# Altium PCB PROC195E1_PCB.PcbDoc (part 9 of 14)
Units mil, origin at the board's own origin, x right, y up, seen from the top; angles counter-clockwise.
Board outline 3110.24 x 2500 mil, 10 copper layers (Top Layer, L02_GND1, L03_SIG1, L04_GND2, L05_PWR1, L06_PWR2, L07_GND3, L08_SIG2, L09_GND4, Bottom Layer), stack 66.407 mil thick; 571 components, 538 nets, 6726 pads, 1286 vias.
Unrouted connection lines stored in the file: 4.
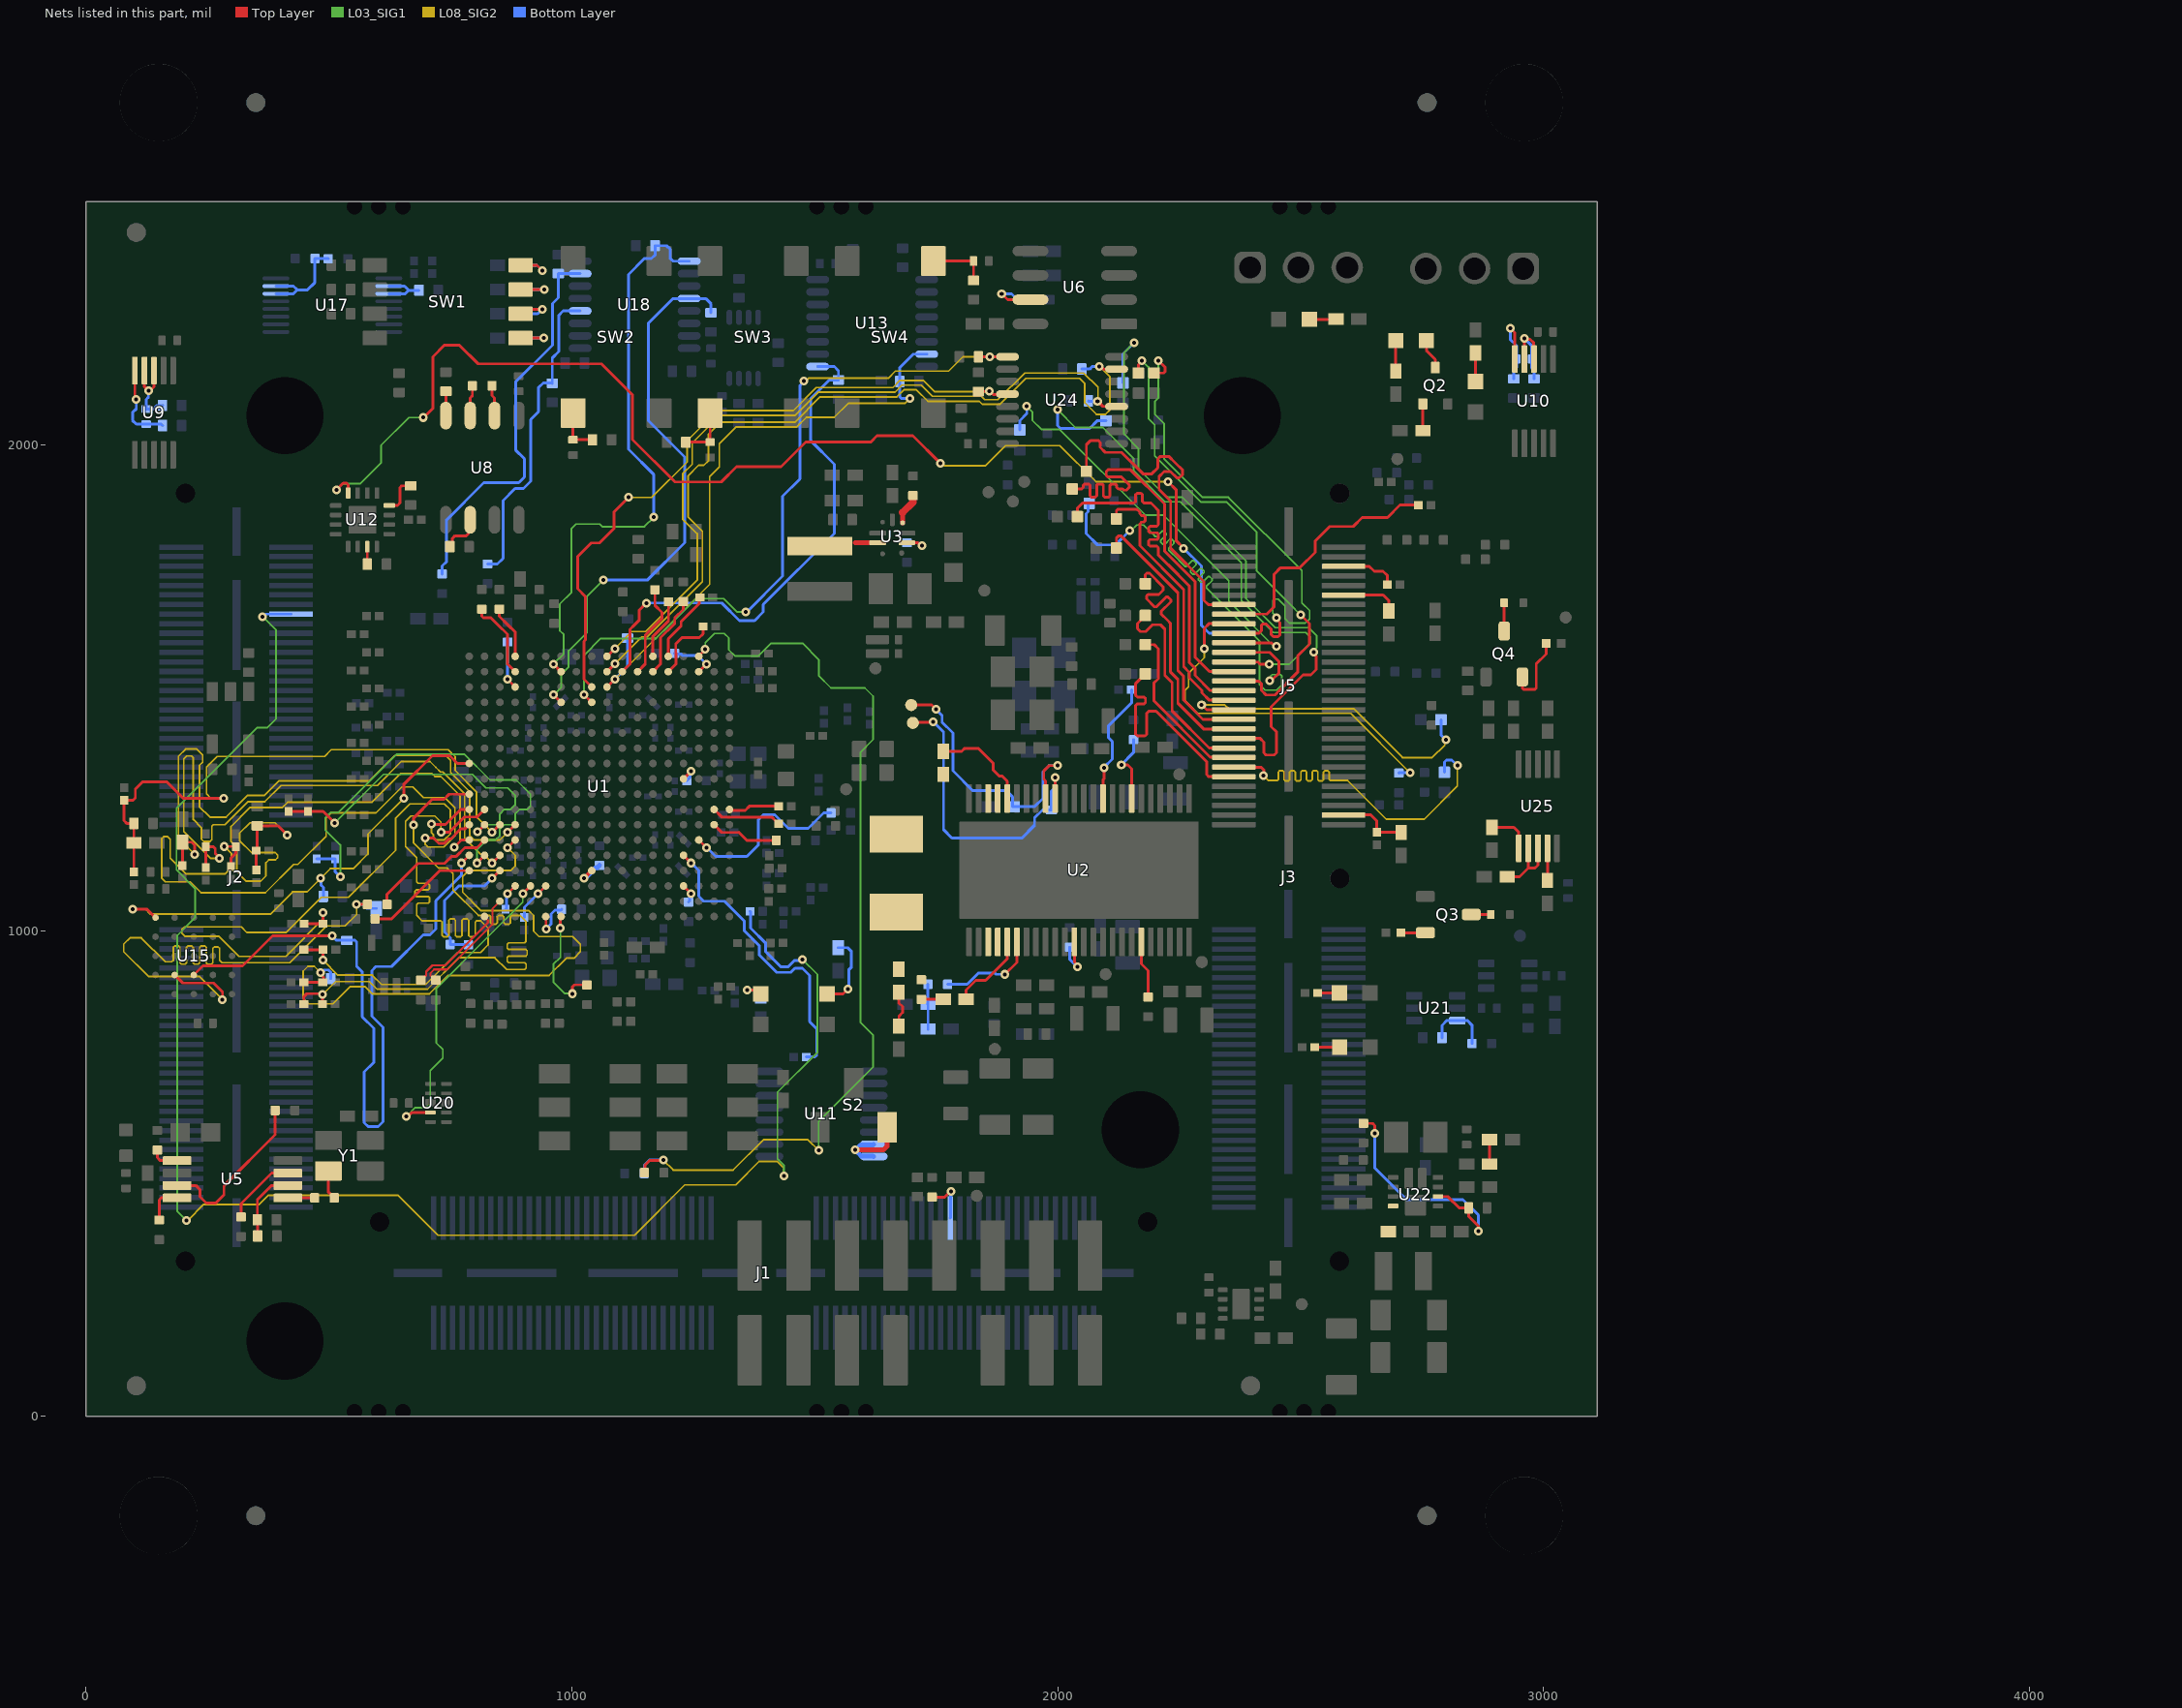
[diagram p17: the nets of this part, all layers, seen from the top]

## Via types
v1: diameter 18, hole 8, Top Layer to Bottom Layer, tented both sides, 1226 vias
v2: diameter 19.68, hole 7.87, Top Layer to Bottom Layer, tented top, 54 vias
v3: diameter 19.68, hole 7.87, Top Layer to Bottom Layer, 4 vias
v4: diameter 19.68, hole 7.87, Top Layer to Bottom Layer, tented both sides, 2 vias

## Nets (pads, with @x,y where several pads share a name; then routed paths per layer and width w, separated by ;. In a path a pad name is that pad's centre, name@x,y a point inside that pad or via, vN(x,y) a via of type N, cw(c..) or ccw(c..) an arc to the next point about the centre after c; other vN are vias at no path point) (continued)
MCU_SPI0_D0: R226.1 R299.2 U1.C10 U13.7 | length 1271.8
  Top Layer w5.8: U1.C10@1072.63,1501.41 v1(1088.66,1517.44)
  L08_SIG2 w3.6: v1(1088.66,1517.44) 1283.98,1712.77 1283.98,1934.28 1303.93,1954.22 1303.93,2002.31 1338.39,2036.77 1463.19,2036.77 1482.92,2056.5 1540.27,2056.5 1569.03,2085.26 1685.76,2085.26 v1(1695.92,2095.42)
  Bottom Layer w5.8: v1(1088.66,1517.44) 1114.68,1543.47 R226.1@1114.68,1602.08 ; v1(1695.92,2095.42) 1678.47,2095.42 1675.07,2098.81 R299.2@1675.07,2130.44 1675.07,2158.63 1702.91,2186.48 U13.7@1730.57,2186.48
MCU_SPI0_D1: R300.2 U1.B11 U13.9 | length 1082.7
  Top Layer w5.66: 1119.92,1548.7 1119.92,1620.04
  Top Layer w5.8: U1.B11@1104.12,1532.91 1119.92,1548.7 ; 1119.92,1620.04 1129.52,1629.65 1139.3,1639.42 1139.3,1660.14 v1(1153.41,1674.25)
  Bottom Layer w5.8: v1(1153.41,1674.25) 1308.81,1674.25 1344.92,1638.15 1376.39,1638.15 1394.1,1655.86 1394.1,1671.16 1540.39,1817.45 1540.39,1959.78 1492.03,2008.14 1492.03,2095.28 1530.01,2133.25 R300.2@1548.89,2133.25 1548.89,2152.32 1540.32,2160.89 U13.9@1506.16,2160.89
MCU_SPI1_CLK: R254.2 U1.A10 U24.4 | length 1577.5
  Top Layer w5.8: U1.A10@1072.63,1564.41 v1(1088.66,1580.43) ; v1(2082.07,2089.77) 2093.01,2078.83 U24.4@2121.29,2078.83
  L08_SIG2 w3.6: v1@1088.38,1580.15 1123.67,1615.45 1152.51,1615.45 1166.71,1629.65 1258.31,1721.25 1258.31,1817.19 1228.45,1847.05 1228.45,1940.27 1248.04,1959.86 1248.04,2003.69 1305.12,2060.77 1460.03,2060.77 1507.42,2108.15 1665.01,2108.15 1679.63,2122.78 1719.58,2122.78 1742.44,2099.92 1842.99,2099.92 1850.19,2092.72 1877.17,2092.72 1932.26,2147.81 2053.54,2147.81 2082.97,2118.37 2082.97,2090.67 v1(2082.07,2089.77)
  Bottom Layer w5.8: R254.2@2063.23,2090.36 2063.82,2089.77 v1(2082.07,2089.77)
MCU_SPI1_CS0: R257.2 U1.C9 U24.12 | length 1398.2
  Top Layer w5.6: R257.2@1836.89,2109.52 1837.13,2109.76 1858.76,2109.76 v1(1859,2110) 1860.86,2110 1867.43,2103.43 1895.9,2103.43 U24.12@1896.89,2104.42
  Top Layer w5.66: 1025.39,1517.16 1025.39,1583.86
  Top Layer w5.8: 1025.39,1517.16 U1.C9@1041.13,1501.41 ; 1025.39,1583.86 1025.39,1595.48 1027.98,1598.08 1027.98,1687.72 1012.16,1703.54 1012.16,1769.99 1040,1797.83 1057.14,1797.83 1086.7,1827.39 1086.7,1861.27 v1(1117.15,1891.72)
  L08_SIG2 w3.6: v1(1117.15,1891.72) 1164.63,1891.72 1237.48,1964.57 1237.48,2008.4 1299.44,2070.37 1456.06,2070.37 1503.44,2117.75 1661.03,2117.75 1675.66,2132.38 1723.55,2132.38 1746.41,2109.52 1858.52,2109.52 v1(1859,2110)
MCU_SPI1_D0: R255.2 U1.B10 U24.7 | length 1744.3
  Top Layer w5.8: U1.B10@1072.63,1532.91 v1(1088.66,1548.94) ; v1(2085.52,2161.5) 2088.64,2161.5 2094.49,2155.64 U24.7@2121.29,2155.6 U24.7@2121.29,2155.6
  L08_SIG2 w3.6: v1@1088.66,1548.81 1144.5,1604.65 1155.41,1604.65 1180.41,1629.65 1269.11,1718.35 1269.11,1821.67 1239.25,1851.53 1239.25,1935.79 1261.22,1957.77 1271.8,1957.77 1281.64,1967.61 1281.64,2022.02 1305.99,2046.37 1459.21,2046.37 1511.4,2098.55 1668.98,2098.55 1683.61,2113.18 1709.28,2113.18 1733.04,2089.42 1839.03,2089.42 1845.33,2083.12 1881.15,2083.12 1934.57,2136.54 2045.06,2136.54 2055.88,2125.72 2055.88,2086.45 2079.8,2062.52 2098.26,2062.52 2107.65,2071.91 2107.65,2139.37 v1(2085.52,2161.5)
  Bottom Layer w5.8: R255.2@2049.59,2155.79 2065.99,2155.79 2071.7,2161.5 v1(2085.52,2161.5)
MCU_SPI1_D1: R256.2 U1.D9 U24.9 | length 1484.5
  Top Layer w5.8: v1(1025.39,1485.67) U1.D9@1041.13,1469.92 ; R256.2@1836.89,2181.04 R256.2@1836.89,2181.04 v1(1860,2181) 1860.1,2181.1 1896.79,2181.1 U24.9@1896.89,2181.19
  L03_SIG1 w3.6: v1(1025.39,1485.67) 1025.39,1566.52 1060.07,1601.21 1173.8,1601.21 1202.24,1629.65 1256.05,1683.46 1312.55,1683.46 1339.97,1656.05 v1(1358.09,1656.05)
  L08_SIG2 w3.6: v1(1477.89,2130.9) 1481.15,2130.9 1487.2,2136.95 1651.38,2136.95 1666.1,2151.67 1775.68,2151.67 1805.01,2181 v1(1860,2181)
  Bottom Layer w5.8: v1(1358.09,1656.05) 1360.61,1656.05 1434.07,1729.51 1434.07,1894.23 1469.45,1929.62 1469.45,2121.93 1477.89,2130.38 v1(1477.89,2130.9)
MCU_SPI3_CLK: R204.1 R304.2 U18.4 | length 654.5
  Bottom Layer w5.8: R204.1@826.74,1754.62 847.1,1754.62 858.63,1766.16 858.63,1885.18 883.43,1909.99 900.71,1909.99 915.67,1924.95 915.67,2051.86 931.88,2068.06 931.88,2117.97 941.39,2127.47 959.11,2127.47 R304.2@960.1,2126.49 960.1,2178.68 973.52,2192.1 973.52,2266.35 982.6,2275.43 U18.4@1017.3,2275.43
MCU_SPI3_CS0: R308.2 U1.D7 U18.12 | length 1156.3
  Top Layer w5.8: v1(962.39,1485.67) U1.D7@978.14,1469.92
  L03_SIG1 w3.6: v1@962.72,1484.75 978.19,1500.22 978.19,1527.3 993.71,1542.81 993.71,1575.91 1031.54,1613.74 1031.54,1629.65 1031.54,1687.97 v1(1065.52,1721.96)
  Bottom Layer w5.8: v1(1065.52,1721.96) 1156.28,1721.96 1232.5,1798.18 1232.5,1975.02 1157.91,2049.61 1157.91,2250.21 1208.72,2301.02 U18.12@1241.71,2301.02 1275.72,2301.02 1286.71,2290.02 R308.2@1286.71,2271.71
MCU_SPI3_D0: R207.1 R306.2 U18.7 | length 819.4
  Bottom Layer w5.8: R207.1@733.39,1734.02 733.39,1750.27 742.03,1758.91 742.03,1844.9 819.13,1922 891.1,1922 902.67,1933.57 902.67,1971.13 884.48,1989.33 884.48,2129.16 960.52,2205.2 960.52,2290.74 972.3,2302.51 R306.2@972.3,2352.2 U18.7@1017.3,2352.2
MCU_SPI3_D1: R307.2 U1.B7 U18.9 | length 1213.4
  Top Layer w5.8: v1(962.39,1548.66) U1.B7@978.14,1532.91 U1.B7@977.86,1532.91
  L03_SIG1 w3.6: v1(962.39,1548.66) 983.57,1569.83 983.57,1609.21 975.51,1617.27 975.51,1629.65 975.51,1672.21 999.61,1696.31 999.61,1827.37 1008.96,1836.72 1057.32,1836.72 1062.62,1831.43 1149.71,1831.43 v1(1169.12,1850.84)
  Bottom Layer w5.8: v1(1169.12,1850.84) 1168.41,1851.55 1168.41,1939.22 1116.76,1990.87 1116.76,2350.63 1149.37,2383.24 1163.95,2383.24 1171.5,2390.8 R307.2@1171.5,2409.8 1195.39,2409.8 1202.47,2402.72 1202.47,2383.79 1208.47,2377.79 U18.9@1241.71,2377.79
MII_RST#: J3.101 U12.4 | length 2647.5
  Top Layer w5.8: v1(515.76,1907.4) 516.2,1907.4 529.7,1920.9 537.15,1920.9 540.02,1918.03 U12.4@540.02,1900.61 ; v1(694.43,2056.01) 695.41,2056.01 714.25,2074.85 714.25,2181.28 737.55,2204.58 769.42,2204.58 807.45,2166.54 1061.43,2166.54 1125.13,2102.85 1125.13,2010.93 1212.61,1923.44 1307.84,1923.44 1339.11,1954.72 1430.76,1954.72 1481.87,2005.82 1615.86,2005.82 1628.41,2018.37 1702.11,2018.37 v1@1758.33,1962.14 ; v1(2227,1924) 2244.34,1906.66 2244.34,1801.94 2258.88,1787.39 v1(2258.88,1786.55)
  L03_SIG1 w3.6: v1(515.76,1907.4) 528.6,1920.24 565.48,1920.24 607.64,1962.4 607.64,1998.65 665,2056.01 v1(694.43,2056.01)
  L08_SIG2 w3.6: v1(1758.33,1961.86) 1762.23,1961.86 1767.54,1956.56 1851.09,1956.56 1892.74,1998.2 2004.52,1998.2 2078.72,1924 v1(2227,1924)
  Bottom Layer w5.8: v1(2258.88,1786.55) 2259.38,1786.55 2295.6,1750.33 2295.6,1628.43 2312.04,1611.99 J3.101@2362.59,1611.99
MII_RX_ER: J2.15 R4.1 | length 3509.3
  L03_SIG1 w3.6: v1(207.32,403.15) 188.53,421.94 188.53,990.22 225.01,1026.7 225.01,1086.76 186.59,1125.18 186.59,1252.01 352.16,1417.59 373.06,1417.59 391.67,1436.19 391.67,1618.24 v1(363.9,1646.01) ; v1(1436.52,495.2) 1436.62,495.3 1436.62,517.39 1423.56,530.44 1423.56,667.32 1505.72,749.47 1505.72,909.59 1474.96,940.34 v1(1474.96,940.53)
  L08_SIG2 w3.6: v1(207.32,403.15) 209.44,403.15 242.69,436.39 357.11,436.39 376.16,455.44 642.48,455.44 724.97,372.95 1129.14,372.95 1232.57,476.38 1337.38,476.38 1386,525 1422.69,525 1436.52,511.17 v1(1436.52,495.2)
  Bottom Layer w5.8: v1(363.9,1646.01) 365.65,1646.01 371.1,1651.47 J2.15@422.38,1651.47 ; R4.1@1367.16,1039.53 1367.81,1038.88 1367.81,1005.49 1399.34,973.96 1399.34,956.31 1429.82,925.82 1445.9,925.82 1458.27,938.19 1472.63,938.19 v1(1474.96,940.53)
MIPI_DETECT: J5.58 R31.2 R260.1 | length 147.5
  Top Layer w5.8: J5.58@2588.18,1237.97 2588.27,1238.06 2644.8,1238.06 2656.82,1226.05 R31.2@2656.82,1202.18 R260.1@2706.82,1202.18
MIPI_TRC_CLK[0]: J5.13 R93.2 | length 755.8
  Top Layer w5.8: R93.2@2059.11,1945.34 2059.11,2000.11 2067.25,2008.25 2084.38,2008.25 2087.77,2004.85 2087.77,1994.7 2098.18,1984.28 2131.48,1984.28 2175.57,1940.2 2193.66,1940.2 2205.98,1952.52 2205.98,1970.98 2210.44,1975.44 2229.72,1975.44 2241.24,1963.92 2241.24,1963.76 2257.34,1947.66 2257.34,1939.07 2250.18,1931.92 2245.38,1931.92 2232.14,1945.16 2219.27,1945.16 2208.57,1934.45 2208.57,1908.28 2232.54,1884.31 2232.54,1787.14 2301.07,1718.6 2301.07,1680.1 2310,1671.17 2310,1671.04 J5.13@2362.59,1671.04
MIPI_TRC_DATA_00: J5.17 R96.2 | length 777.9
  Top Layer w5.8: v1(2301.74,1580.31) 2301.74,1622.19 2311.22,1631.67 J5.17@2362.59,1631.67
  L08_SIG2 w3.6: v1(2301.74,1580.31) 2301.74,1561.74 2269.54,1529.54 2269.54,1501.7 2261.7,1493.86 2261.7,1473.7 2288.29,1447.11 2603.01,1447.11 v1(2725.02,1325.11)
  Bottom Layer w5.8: R96.2@2702.18,1324.23 2702.62,1324.67 2724.58,1324.67 v1(2725.02,1325.11)
MIPI_TRC_DATA_01: J5.19 R98.2 | length 1070.1
  Top Layer w5.8: R98.2@2198.4,2147.57 2217.97,2147.57 2220.84,2150.44 2220.84,2159.79 v1(2207.37,2173.26) ; J5.19@2362.59,1611.99 2413.99,1611.99 2419,1617 2419,1628.13 2421.87,1631 2429.31,1631 2439.48,1620.84 2439.48,1609.64 2443.96,1605.15 2453.62,1605.15 2457.02,1608.55 2457.02,1634.19 2450.54,1640.67 v1(2450.54,1643.97)
  L03_SIG1 w3.6: v1@2207.4,2173.23 2207.4,2097.01 2200.42,2090.03 2200.42,2062.2 2218.86,2043.76 2218.86,1971.32 2298.33,1891.86 2351.52,1891.86 2502.55,1740.82 2502.55,1674.65 2518.38,1658.82 2518.38,1641.7 2509.63,1632.95 2476.97,1632.95 2467.76,1642.16 2467.76,1668.58 2453.88,1682.46 2445.52,1682.46 2442.93,1679.87 2442.93,1653.14 2450.54,1645.53 v1(2450.54,1643.97)
MIPI_TRC_DATA_02: J5.21 R99.2 | length 899.6
  Top Layer w5.8: J5.21@2362.59,1592.3 2440.33,1592.3 2447.75,1584.88 v1(2450.54,1584.88)
  L03_SIG1 w3.6: v1(1936.5,2079.39) 1947.94,2067.95 1947.94,2050.55 1966.7,2031.79 2003.69,2031.79 2180.3,1855.18 2217.18,1855.18 2352.01,1720.35 2352.01,1678.01 2441.26,1588.76 2442.75,1588.76 2446.64,1584.88 v1(2450.54,1584.88)
  Bottom Layer w5.8: R99.2@1922,2030.67 1922,2049.7 1936.5,2064.2 v1(1936.5,2079.39)
MIPI_TRC_DATA_03: J5.23 R100.2 | length 1073.4
  Top Layer w5.8: J5.23@2362.59,1572.62 2436.33,1572.62 2455.05,1553.9 2455.05,1529.82 2448.58,1523.35 2448.35,1523.35 2439.65,1514.65 v1(2436.35,1514.65)
  L03_SIG1 w3.6: v1(2148.45,1823.35) 2151.3,1823.35 2162.65,1834.69 2177,1834.69 2199.26,1812.43 2200.54,1811.16 2203.82,1811.16 2214.68,1822.02 2217.96,1822.02 2222.88,1817.1 2222.88,1813.81 2212.02,1802.95 2212.02,1799.67 2216.94,1794.75 2220.22,1794.75 2231.08,1805.61 2234.36,1805.61 2239.29,1800.69 2239.29,1797.41 2228.42,1786.55 2228.42,1783.27 2235.75,1775.94 2237.02,1774.67 2260.61,1751.09 2261.88,1749.81 2265.16,1749.81 2276.7,1761.36 2279.98,1761.36 2284.9,1756.43 2284.9,1753.15 2273.36,1741.61 2273.36,1738.33 2278.28,1733.41 2281.56,1733.41 2293.11,1744.95 2296.39,1744.95 2301.31,1740.03 2301.31,1736.75 2289.77,1725.21 2289.77,1721.93 2294.69,1717 2297.97,1717 2309.51,1728.55 2312.79,1728.55 2317.71,1723.63 2317.71,1720.34 2306.17,1708.8 2306.17,1705.52 2319.07,1692.62 2320.35,1691.35 2415.24,1596.46 2415.24,1506.97 2427.21,1495 2450.66,1495 2461,1505.34 2461,1524.82 2458.89,1526.93 2441.45,1526.93 2439.11,1524.58 2439.11,1517.4 v1(2436.35,1514.65)
  Bottom Layer w5.8: R100.2@2065.1,1879.35 2062.83,1877.07 2062.83,1862.23 2058.49,1857.89 2058.49,1817.44 2082.06,1793.87 2118.97,1793.87 v1(2148.45,1823.35)
MIPI_TRC_DATA_04: J5.25 R101.2 | length 1105.4
  Top Layer w5.8: J5.25@2362.59,1552.93 2362.68,1552.85 2412.22,1552.85 2416.8,1548.27 v1@2435.37,1548.27
  L03_SIG1 w3.6: v1(2000.05,2072.21) 2036.64,2035.61 2092.61,2035.61 2156.53,1971.69 2156.53,1946.82 2220.83,1882.51 2252.36,1882.51 2377.87,1757.01 2377.87,1679.31 2443.76,1613.41 2510.92,1613.41 2520.63,1603.7 2520.63,1592.21 2476.66,1548.25 v1(2435.39,1548.25)
  Bottom Layer w5.8: v1(2000.05,2072.21) 2000.05,2039.34 2005.71,2033.68 2065.7,2033.68 2081.14,2049.12 R101.2@2099.5,2049.12
MIPI_TRC_DATA_05: J5.27 R102.2 | length 882.9
  Top Layer w5.8: R102.2@2030.07,1909.03 2046.32,1909.03 2049.22,1909.03 2052.62,1912.43 2052.62,1916.53 2055.38,1919.29 2063.66,1919.29 2066.42,1916.53 2066.42,1894.78 2069.18,1892.02 2077.46,1892.02 2080.22,1894.78 2080.22,1916.53 2082.98,1919.29 2091.26,1919.29 2094.02,1916.53 2094.02,1894.78 2096.78,1892.02 2105.06,1892.02 2107.82,1894.78 2107.82,1916.53 2110.58,1919.29 2118.86,1919.29 2121.62,1916.53 2121.62,1912.43 2125.01,1909.03 2133.76,1909.03 2136.3,1906.49 2141.49,1906.49 2147,1912 2147,1918 2131.39,1933.61 2103.4,1933.61 2100,1937.01 2100,1945.14 2103.4,1948.54 2149.93,1948.54 2220.3,1878.17 2220.3,1780.78 2282.95,1718.13 2282.95,1562.72 2312.42,1533.25 J5.27@2362.59,1533.25
MIPI_TRC_DATA_06: J5.29 R103.2 | length 1023.9
  Top Layer w5.8: R103.2@2166.47,2147.99 2166.47,2164.88 2173.51,2171.91 v1(2173.51,2173.38) ; J5.29@2362.59,1513.56 2413.76,1513.56 2419.2,1508.13 2419.2,1494.68 2428.8,1485.07 2447.15,1485.07 2493.75,1531.67 2493.75,1565.1 2517.85,1589.19 2517.85,1631.92 v1(2499.85,1649.91)
  L03_SIG1 w3.6: v1(2173.51,2173.38) 2187.06,2159.84 2187.06,2053.82 2199.47,2041.41 2199.47,1977.14 2294.35,1882.26 2347.54,1882.26 2409.23,1820.57 2409.23,1740.68 2477.36,1672.56 2477.36,1672.41 v1(2499.85,1649.91)
MIPI_TRC_DATA_07: J5.31 R86.1 | length 758
  Top Layer w5.8: R86.1@2040.63,1851.9 2040.63,1869.57 2051.27,1880.22 2154.29,1880.22 2157.19,1880.22 2160.59,1883.61 2160.59,1897.46 2163.35,1900.22 2171.63,1900.22 2174.39,1897.46 2174.39,1883.61 2177.78,1880.22 2191.9,1880.22 2196.98,1875.14 2207.3,1864.82 2207.3,1852.63 2207.3,1835.93 2203.9,1832.53 2190.06,1832.53 2187.3,1829.77 2187.3,1821.49 2190.06,1818.73 2204.54,1818.73 2207.3,1815.97 2207.3,1807.69 2204.54,1804.93 2190.06,1804.93 2187.3,1802.17 2187.3,1793.89 2190.06,1791.13 2203.9,1791.13 2207.3,1787.73 2207.3,1772.89 2209.61,1770.58 2227.26,1752.93 2227.52,1752.93 2271.15,1709.3 2271.15,1551.56 2282.86,1539.85 2282.86,1525.14 2314,1494 2362.47,1494 J5.31@2362.59,1493.88
MIPI_TRC_DATA_08: J5.33 R87.1 | length 579.9
  Top Layer w5.8: R87.1@2120.91,1847.43 2120.91,1864.35 2123.79,1867.22 2162.66,1867.22 2169,1860.88 2169,1857.98 2172.4,1854.58 2177.16,1854.58 2179.92,1851.82 2179.92,1843.54 2177.16,1840.78 2172.4,1840.78 2169,1837.38 2169,1811.78 2169,1792.21 2259.35,1701.86 2259.35,1543.28 2271.06,1531.57 2271.06,1520.25 2297.08,1494.24 2297.08,1489.26 2312.14,1474.19 J5.33@2362.59,1474.19
MIPI_TRC_DATA_09: J5.35 R88.1 | length 683.7
  Top Layer w5.8: v1(2296.29,1464.73) 2296.4,1464.73 2306.62,1454.51 J5.35@2362.59,1454.51
  L08_SIG2 w3.6: v1(2296.29,1464.73) 2296.63,1464.39 2344.08,1464.39 2351.77,1456.71 2608.91,1456.71 2709.57,1356.06 2770.78,1356.06 2796.37,1381.65 2796.37,1390.07 v1(2798.74,1392.44)
  Bottom Layer w5.8: R88.1@2788.84,1434.06 2788.84,1402.34 v1(2798.74,1392.44)
MIPI_TRC_DATA_30: J5.37 R89.1 | length 542.5
  Top Layer w5.8: R89.1@2120.91,1787.43 2120.91,1807.91 2124.97,1811.97 2130.86,1811.97 2247.55,1695.28 2247.55,1535.23 2259.26,1523.52 2259.26,1474.59 2299.02,1434.82 J5.37@2362.59,1434.82
MIPI_TRC_DATA_31: J5.39 R90.1 | length 559.5
  Top Layer w5.8: R90.1@2180.46,1713.93 2180.46,1732.64 2183.33,1735.51 2188.93,1735.51 2217.06,1707.38 2217.06,1700.98 2208.09,1692 2185.87,1692 2183,1689.13 2183,1682.66 2199.24,1666.42 2203.03,1666.42 2223.05,1686.43 2226.95,1686.43 2232.81,1680.58 2232.81,1676.68 2212.79,1656.66 2212.79,1651.86 2225.82,1638.83 2232.39,1632.26 2232.39,1532 2247.46,1516.94 2247.46,1468 2300.33,1415.14 J5.39@2362.59,1415.14
MIPI_TRC_DATA_32: J5.41 R91.1 | length 1340.9
  Top Layer w5.8: J5.41@2362.59,1395.45 2416.93,1395.45 2424.53,1387.85 2424.53,1365.78 2428.89,1361.42 2445.54,1361.42 2450,1365.88 2450,1409.22 2439.33,1419.89 2439.33,1460.56 2505.3,1526.53 2520.94,1526.53 2531.85,1537.44 2531.85,1565.26 2527.19,1569.92 v1(2527.19,1573.22)
  L03_SIG1 w3.6: v1(2157.16,2210.02) 2136.46,2189.32 2136.46,2021.99 2166.13,1992.32 2166.13,1950.79 2224.81,1892.11 2256.34,1892.11 2387.47,1760.98 2387.47,1683.28 2447.4,1623.35 2516.25,1623.35 2533.15,1606.45 2533.15,1582.53 2527.19,1576.57 v1(2527.19,1573.22)
  Bottom Layer w5.8: R91.1@2134.23,2127.18 2134.09,2127.32 2134.09,2186.95 v1(2157.16,2210.02)
MIPI_TRC_DATA_33: J5.43 R92.1 | length 435.4
  Top Layer w5.8: R92.1@2180.46,1648.62 2164.08,1632.25 2164.08,1621.66 2170.12,1615.62 2181.21,1615.62 2195.11,1629.52 2211.44,1629.52 2220.59,1620.36 2220.59,1525.42 2235.49,1510.52 2235.49,1452.11 2311.84,1375.77 J5.43@2362.59,1375.77
MIPI_TRC_DATA_34: J5.45 R94.1 | length 353.6
  Top Layer w5.8: R94.1@2180.46,1588.62 2198.58,1588.62 2206.93,1580.27 2206.93,1518.65 2198.48,1510.2 2198.48,1472.44 2313.85,1357.07 2361.61,1357.07 J5.45@2362.59,1356.08
MIPI_TRC_DATA_35: J5.47 R95.1 | length 814.8
  Top Layer w5.8: J5.47@2362.59,1336.4 2418.57,1336.4 2424,1330.97 v1@2424,1319.62
  L08_SIG2 w3.6: v1(2423.75,1319.35) 2434.18,1308.92 2450.1,1308.92 2451.9,1308.92 2454.22,1311.24 2454.22,1326.6 2456.54,1328.92 2463.5,1328.92 2465.82,1326.6 2465.82,1310.52 2468.14,1308.2 2475.1,1308.2 2477.42,1310.52 2477.42,1326.6 2479.74,1328.92 2486.7,1328.92 2489.02,1326.6 2489.02,1310.52 2491.34,1308.2 2498.3,1308.2 2500.62,1310.52 2500.62,1326.6 2502.94,1328.92 2509.9,1328.92 2512.22,1326.6 2512.22,1310.52 2514.54,1308.2 2521.5,1308.2 2523.82,1310.52 2523.82,1326.6 2526.14,1328.92 2533.1,1328.92 2535.42,1326.6 2535.42,1310.52 2537.74,1308.2 2544.7,1308.2 2547.02,1310.52 2547.02,1326.6 2549.34,1328.92 2556.3,1328.92 2558.62,1326.6 2558.62,1311.24 2560.94,1308.92 2571.45,1308.92 2596.75,1308.92 2676.42,1229.26 2754.14,1229.26 2822.5,1297.62 v1(2822.5,1340.36)
  Bottom Layer w5.8: R95.1@2795.77,1325.77 2795.77,1346.83 2800.14,1351.2 2810.86,1351.2 2821.7,1340.36 v1(2822.5,1340.36)
MIPI_TRC_DATA_36: J5.49 R97.1 | length 486.7
  Top Layer w5.8: R97.1@2180.46,1528.62 2160.64,1508.81 2160.64,1494.77 2160.64,1484.1 2164.04,1480.7 2177.88,1480.7 2180.64,1477.94 2180.64,1469.66 2177.88,1466.9 2164.04,1466.9 2160.64,1463.51 2160.64,1446.81 2160.64,1404.06 2164.04,1400.67 2179.62,1400.67 2183.02,1404.06 2183.02,1447.27 2187.49,1451.74 2202.48,1451.74 2306.73,1347.5 2306.73,1321.19 2311.2,1316.71 J5.49@2362.59,1316.71
MIPI_VREF_TRACE: J5.12 R216.2 | length 119.4
  Top Layer w5.8: J5.12@2588.18,1690.73 2669.8,1690.73 2681.28,1679.24 R216.2@2681.28,1657.69
NetC61_2: C61.2 U22.10
NetC70_1: C70.1 R14.2 | length 76.2
  Top Layer w5.6: C70.1@1673.3,803.27 1673.47,803.44 1673.47,824.14 1680.79,831.46 1680.79,843.42 1673.3,850.9 R14.2@1673.3,873.27
NetC71_1: C71.1 L1.2 U2.45 U2.46
NetC71_2: C71.2 U2.44 | length 205.8
  Top Layer w5.8: C71.2@1764.9,1368.77 1802.47,1368.77 1808.93,1375.23 1836.18,1375.23 1867.64,1343.77 1867.64,1329.98 1879.74,1317.88 1885.94,1317.88 1896.38,1307.44 U2.44@1896.38,1271.95
NetC72_1: C72.1 R15.2 | length 45
  Top Layer w5.8: R15.2@1719.52,858.41 C72.1@1764.52,858.41
NetC72_2: C72.2 U2.5 | length 165.3
  Top Layer w5.8: C72.2@1811.76,858.41 1811.76,877.9 1831.2,897.35 1851.74,897.35 1896.24,941.84 1896.24,976.53 U2.5@1896.38,976.67
NetC81_1: C81.1 TP13.1 U2.39 | length 648.8
  Top Layer w5.8: TP13.1@1702.27,1427.61 1703.51,1428.85 1742.97,1428.85 v1(1744.21,1430.1) ; U2.39@1994.8,1271.95 1994.85,1272 v1(1994.85,1315.05)
  Bottom Layer w5.8: v1(1744.21,1430.1) 1744.21,1429.96 1765.17,1409 1765.17,1207.89 1782.25,1190.81 1926.55,1190.81 1952.49,1216.75 1952.49,1232.13 1968.74,1248.38 C81.1@1987.21,1248.38 1987.21,1287.37 1994.85,1295.02 v1(1994.85,1315.05)
NetC82_2: C82.2 TP15.1 U2.40 | length 612.5
  Top Layer w5.8: TP15.1@1698.58,1464.36 1740.98,1464.36 1749.68,1455.66 v1(1749.95,1455.66) ; U2.40@1975.12,1271.95 1975.12,1308.09 1971.39,1311.82 1971.39,1328.69 1982.26,1339.57 v1(2000.02,1339.57)
  Bottom Layer w5.8: v1(1749.95,1455.66) 1749.95,1454.98 1762.13,1442.8 1762.13,1428.73 1784.33,1406.53 1784.33,1329.24 1825.73,1287.83 1894.56,1287.83 1906.79,1275.6 C82.2@1906.79,1254.92 1952.27,1254.92 1969.68,1272.33 1969.68,1326.64 1982.61,1339.57 v1(2000.02,1339.57)
NetC96_2: C96.2 R45.1 U22.2 | length 529
  Top Layer w5.8: R45.1@2629.27,603.19 2647.9,603.19 2652.61,598.48 2652.61,582.78 v1(2652.82,582.58) ; U22.2@2782.71,452.61 2802.65,452.61 2826.26,429 C96.2@2846.04,429 ; C96.2@2846.04,429.38 C96.2@2846.04,429 ; v1(2865.79,380.95) 2865.79,391.85 2846.04,411.61 C96.2@2846.04,429
  Bottom Layer w5.8: v1(2652.82,582.58) 2652.82,511.37 2717.82,446.36 2834.09,446.36 2865.79,414.66 v1(2865.79,380.95)
NetC103_2: C103.2 R192.1 | length 50
  Top Layer w5.8: R192.1@2888.9,519.48 C103.2@2888.9,569.48
NetC120_1: C120.1 R66.2 U9.10 | length 172.9
  Top Layer w5.8: U9.10@101.14,2152.59 101.14,2099.39 103.97,2096.55 v1(103.97,2093.25)
  Bottom Layer w5.8: v1(103.97,2093.25) 103.97,2073.95 96.22,2066.2 96.22,2050.2 104.17,2042.25 C120.1@124.44,2042.25 155.29,2042.25 R66.2@157.98,2039.56
NetC120_2: C120.2 R70.2 U9.8 U9.9 | length 169.2
  Top Layer w5.8: U9.9@120.82,2152.59 120.82,2119.59 v1(129.4,2111.01) 132.42,2111.01 140.51,2119.1 U9.8@140.51,2152.59
  Bottom Layer w5.8: v1(129.4,2111.01) 128.99,2110.6 128.99,2097.99 124.44,2093.44 C120.2@124.44,2073.75 124.78,2073.41 139.41,2073.41 146,2080 156.97,2080 R70.2@157.98,2081.01
NetC121_1: C121.1 R67.2 U10.10 | length 179.4
  Top Layer w5.8: v1@2931.56,2240.06 2940.53,2231.09 U10.10@2940.53,2176.41
  Bottom Layer w5.8: v1(2931.53,2240.06) 2931.53,2216.5 2944.29,2203.74 2944.29,2158.92 2938.78,2153.41 R67.2@2938.78,2135.66
NetC121_2: C121.2 R71.2 U10.8 U10.9 | length 192.7
  Top Layer w5.8: U10.9@2960.42,2176.2 2960.21,2176.41 2960.21,2216.91 2960.21,2219.03 v1(2960,2219.24) 2962.33,2216.91 2972.66,2216.91 2979.73,2209.84 2979.73,2176.57 U10.8@2980.11,2176.2
  Bottom Layer w5.8: v1(2960,2219.24) 2975.79,2203.45 C121.2@2975.79,2176.53 2975.79,2157.73 2980.39,2153.12 R71.2@2980.39,2135.66
NetC155_1: C155.1 R245.2 SW2.4 | length 95
  Top Layer w5.8: SW2.4@1002.73,2065.26 C155.1@1002.73,2010.26 R245.2@1042.73,2010.26
NetC158_1: C158.1 R250.2 SW3.4 | length 110
  Top Layer w5.8: R250.2@1234.9,2005.26 C158.1@1284.9,2005.26 SW3.4@1284.9,2065.26
NetC159_1: C159.1 R252.2 SW4.4 | length 122.7
  Top Layer w5.8: SW4.4@1744.23,2378.25 C159.1@1826.89,2378.25 R252.2@1826.89,2338.25
NetD2_2: D2.2 R47.1 | length 157
  Top Layer w5.8: D2.2@1525.61,869.88 1558.23,869.88 v1(1567.97,879.63)
  Bottom Layer w5.8: R47.1@1548.35,964.8 1568,964.8 1574.95,957.85 1574.95,923.88 1570.06,918.99 1570.06,881.72 v1(1567.97,879.63)
NetD3_2: D3.2 R48.1 | length 66.3
  Top Layer w5.8: v1(1361,878) 1380.67,878 D3.2@1388.78,869.88
  Bottom Layer w5.8: v1(1361,878) 1379.87,878 1388.78,869.09 R48.1@1388.78,865.36
NetD4_1: D4.1 Q2.3 | length 63.2
  Top Layer w5.8: D4.1@2758.78,2214.42 D4.1@2758.78,2214.42 2758.83,2193.64 2761.7,2190.77 2761.76,2190.77 2777.11,2175.42 Q2.3@2777.11,2158.83
NetD4_2: D4.2 R57.2 | length 62.6
  Top Layer w5.8: R57.2@2695.79,2151.82 D4.2@2695.79,2214.42
NetD5_2: D5.2 R58.2 | length 51.3
  Top Layer w5.8: R58.2@2528.83,759.91 D5.2@2580.12,759.91
NetD6_2: D6.2 R68.2 | length 58.8
  Top Layer w5.8: D6.2@2859.8,2130.15 R68.2@2859.8,2188.94
NetD7_2: D7.2 R72.2 | length 55
  Top Layer w5.8: D7.2@2517.87,2258.07 2572.22,2258.07 R72.2@2572.68,2258.53
NetD8_2: D8.2 R160.2 | length 44.9
  Top Layer w5.8: R160.2@2534.66,871.87 D8.2@2579.61,871.87
NetD9_2: D9.2 Q3.3 | length 40
  Top Layer w5.8: Q3.3@2851.22,1033.04 D9.2@2891.22,1033.04
NetD10_2: D10.2 Q4.3 | length 58.2
  Top Layer w5.8: Q4.3@2918.89,1616.59 D10.2@2918.89,1674.75
NetJ1_32: J1.32 R74.1 | length 99.1
  Top Layer w5.8: R74.1@1741.7,451.37 1767.12,451.37 1778.84,463.09 v1(1780.42,463.09)
  Bottom Layer w5.8: J1.32@1778.96,408.19 1779.69,408.92 1779.69,462.35 v1(1780.42,463.09)
NetJ5_15: J5.15 R26.2 | length 525.2
  Top Layer w5.8: J5.15@2362.59,1651.36 2430.06,1651.36 2444.99,1666.28 2444.99,1733.04 2458.86,1746.92 2498.37,1746.92 2529.94,1778.48 2529.94,1801.94 2559.87,1831.86 2608.33,1831.86 2626.66,1850.19 2678.79,1850.19 2704.49,1875.9 R26.2@2741.95,1875.9
NetL1_1: L1.1 R14.1 R15.1 U2.3 U2.4
NetL2_1: L2.1 U3.2 | length 46.8
  Top Layer w10: 1583,1798.32 U3.2@1629.79,1798.32
NetQ2_1: Q2.1 R265.2 | length 55.1
  Top Layer w5.8: R265.2@2751.52,2028.96 Q2.1@2751.52,2084.02
NetQ3_2: Q3.2 R279.1 | length 50
  Top Layer w5.8: R279.1@2706.73,995.64 Q3.2@2756.73,995.64
NetQ4_2: Q4.2 R280.1 | length 154.2
  Top Layer w5.8: Q4.2@2956.29,1522.1 2956.13,1521.94 2956.13,1499.56 2959.53,1496.16 2981.53,1496.16 2984.93,1499.56 2984.93,1549.3 3005.02,1569.39 R280.1@3005.02,1591.21
NetR3_1: R3.1 U5.3 | length 150.2
  Top Layer w5.8: R3.1@319.67,410.56 319.67,438.35 382.29,500.97 U5.3@416.14,500.97
NetR9_2: R9.2 U1.R9 | length 65.1
  Top Layer w8: v1(1025.39,1107.71) U1.R9@1041.13,1123.46
  Bottom Layer w10: v1(1025.39,1107.71) 1026.92,1109.24 1029.1,1109.24 1049.82,1129.96 1052.86,1129.96 R9.2@1057.21,1134.31
NetR11_2: R11.2 U1.J15 | length 45.6
  Top Layer w5.8: U1.J15@1230.11,1312.44 v1(1245.86,1328.19)
  Bottom Layer w5.8: R11.2@1236.78,1308.66 1243.23,1315.11 1243.23,1322.26 1245.86,1324.88 v1(1245.86,1328.19)
NetR16_1: R16.1 R17.2 R18.2 | length 92.1
  Bottom Layer w5.8: R18.2@1733.09,889.41 1733.09,848.34 R17.2@1733.23,848.2 R16.1@1733.24,797.34
NetR18_1: R18.1 U2.6 | length 205.4
  Top Layer w5.8: v1(1891.47,910.02) 1916.06,934.61 U2.6@1916.06,976.67
  Bottom Layer w5.8: R18.1@1773.45,889.41 1813.89,889.41 1836.89,912.42 1870.87,912.42 1873.27,910.02 v1(1891.47,910.02)
NetR23_2: R23.2 U2.19 | length 119.2
  Top Layer w5.8: U2.19@2171.97,976.67 2171.97,931.37 2185.94,917.4 R23.2@2185.94,863.3
NetR24_2: R24.2 U2.34 | length 254.1
  Top Layer w5.8: U2.34@2093.23,1271.95 2093.23,1310.23 2095.12,1312.12 v1(2095.12,1335.34)
  Bottom Layer w5.8: v1(2095.12,1335.34) 2112.51,1352.73 2112.51,1389.23 2104.83,1396.92 2104.83,1421.81 2152.04,1469.02 R24.2@2152.04,1495.35
NetR25_1: R25.1 U2.31 | length 148.3
  Top Layer w5.8: v1(2130.92,1341.27) 2131,1341.19 2144.28,1341.19 2152.28,1333.19 U2.31@2152.28,1271.95
  Bottom Layer w5.8: v1(2130.92,1341.27) 2155.94,1366.28 R25.1@2155.94,1393.29
NetR27_2: R27.2 U3.5 | length 67.3
  Top Layer w5.8: U3.5@1689.83,1798.32 1712.39,1798.32 1718.6,1792.1 v1(1720.89,1792.1)
  Bottom Layer w5.8: R27.2@1689.83,1798.32 1712.78,1798.32 1718.99,1792.1 v1(1720.89,1792.1)
NetR28_1: R28.1 U2.12 | length 100.5
  Top Layer w5.8: U2.12@2034.17,976.67 2034.56,976.28 2034.56,934.75 2040.41,928.9 v1(2040.41,925.6)
  Bottom Layer w5.8: R28.1@2024.45,965.83 2024.45,941.56 v1(2040.41,925.6)
NetR35_2: R35.2 U3.7 | length 65.2
  Top Layer w10: U3.7@1680.97,1839.16 1680.97,1860.54
  Top Layer w15: 1680.97,1860.54 1702.27,1881.84 R35.2@1702.27,1895.53
NetR36_1: R36.1 Y1.3 | length 61.1
  Top Layer w5.8: Y1.3@499.33,505.16 498.83,504.65 498.83,462.46 504.56,456.73 505.05,456.73 511.5,450.28 R36.1@511.5,449.79
NetR36_2: R36.2 U5.1 | length 55
  Top Layer w5.8: U5.1@416.14,449.79 R36.2@471.14,449.79
NetR38_2: R38.2 U1.A13 | length 125.7
  Top Layer w5.8: U1.A13@1167.12,1564.41 1167.12,1605.57 1191.2,1629.65 1199.16,1637.61 R38.2@1199.16,1676.85
NetR39_2: R39.2 U1.B13 | length 170.3
  Top Layer w5.66: 1182.82,1548.61 1182.82,1602.98
  Top Layer w5.8: U1.B13@1167.12,1532.91 1182.82,1548.61 ; 1182.82,1602.98 1209.48,1629.65 1212.16,1632.32 1212.16,1643.69 1229.58,1661.11 R39.2@1229.58,1677.36
NetR46_1: R46.1 R51.2 U5.2 | length 150
  Top Layer w5.8: R51.2@353.13,404.71 353.13,446.12 382.39,475.38 U5.2@416.14,475.38 ; R51.2@353.5,404.71 353.5,371.76 R46.1@353.87,371.39
NetR52_1: R52.1 U5.7 | length 344.8
  Top Layer w5.8: U5.7@187.8,475.38 226.52,475.38 235.31,466.59 235.31,451.95 248.24,439.03 267.55,439.03 284.45,455.93 284.45,474.42 389.82,579.79 R52.1@389.82,629.77
NetR53_2: R53.2 U1.R1 | length 234.4
  Top Layer w5.8: R53.2@595.67,1024.24 629.39,1024.24 720.46,1115.32 728.47,1123.32 U1.R1@789.02,1123.32
NetR54_2: R54.2 U8.6 | length 86.1
  Top Layer w5.8: R54.2@749.42,1790.23 754.06,1794.87 754.06,1806.8 759.93,1812.67 783.03,1812.67 787.73,1817.36 787.73,1842.08 U8.6@791.14,1845.49
NetR55_2: R55.2 U8.4 | length 50
  Top Layer w5.8: U8.4@741.14,2060.06 R55.2@741.14,2110.06
NetR56_1: R56.1 U8.2 | length 63.6
  Top Layer w5.8: R56.1@835.99,2121.54 835.99,2101.23 841.14,2096.08 U8.2@841.14,2060.06
NetR56_2: R56.2 U8.3 | length 63.3
  Top Layer w5.8: U8.3@791.14,2060.06 791.14,2096.5 795.63,2101 R56.2@795.63,2121.54
NetR69_1: R69.1 U6.7 | length 128.4
  Top Layer w5.8: v1(1884.77,2310.62) 1885.01,2310.62 1897.02,2298.61 U6.7@1944.01,2298.61
  Bottom Layer w5.8: v1(1884.77,2310.62) 1905.42,2310.62 1917.43,2298.61 R69.1@1944.01,2298.61
NetR73_1: R73.1 U1.V6 | length 86.2
  Top Layer w5.8: U1.V6@946.64,1028.97 947.15,1028.47 947.15,1004.01 v1(947.66,1003.5)
  Bottom Layer w5.8: v1(947.66,1003.5) 957.76,1013.6 957.76,1034.31 965.8,1042.35 977.78,1042.35 R73.1@979.18,1043.74
NetR75_1: R75.1 U1.V7 | length 235.8
  Top Layer w5.8: v1(976.79,1005.35) 976.86,1005.42 976.86,1027.69 U1.V7@978.14,1028.97 ; v1(1001.03,870.15) 1001.03,883.7 1005.38,888.05 R75.1@1031.59,888.05
  L03_SIG1 w3.6: v1(976.79,1005.35) 976.79,987.34 976.79,945.1 962.39,930.71 962.39,894.23 986.23,870.39 1000.8,870.39 v1(1001.03,870.15)
NetR76_2: R76.2 U1.B16 | length 97
  Top Layer w5.8: U1.B16@1261.61,1533.2 U1.B16@1261.61,1532.91 v1(1277.35,1548.66)
  Bottom Layer w5.8: R76.2@1211.89,1570.78 1213.77,1568.89 1225.27,1568.89 1227.6,1566.56 1253.4,1566.56 1253.52,1566.44 1259.57,1566.44 1276.69,1549.32 v1@1276.69,1548.57
NetR77_1: R77.1 U1.T15 | length 42.9
  Top Layer w5.8: U1.T15@1230.11,1091.97 v1(1245.86,1076.22)
  Bottom Layer w5.8: R77.1@1240.7,1058.72 1242.94,1060.96 1242.94,1075.28 v1@1245.18,1077.52
NetR80_1: R80.1 U12.11 | length 36.1
  Top Layer w5.8: R80.1@579.39,1754.31 U12.11@579.39,1790.38
NetR81_1: R81.1 U12.16 | length 79.2
  Top Layer w5.8: U12.16@624.67,1875.02 641.51,1875.02 646.92,1880.43 646.92,1912 650.31,1915.4 R81.1@668.63,1915.4
NetR83_2: R83.2 U1.B14 | length 143.5
  Top Layer w5.66: 1214.26,1590.12 1214.26,1570.97 1214.32,1570.91 1214.32,1557.9
  Top Layer w5.8: U1.B14@1198.61,1532.91 1214.26,1548.56 1214.26,1557.85 1214.32,1557.9 ; 1214.26,1590.12 1227.1,1602.96 1236.41,1602.96 1262.49,1602.96 1270.21,1610.68 R83.2@1270.21,1625.99
NetR84_1: R84.1 R138.1 U1.M2 | length 684.4
  Top Layer w5.8: R84.1@417.42,1245.48 R138.1@457.42,1245.48 488.61,1245.48 v1(512.55,1221.55) ; v1(806.49,1203.11) 806.49,1203.44 820.66,1217.62 U1.M2@820.66,1217.95
  L03_SIG1 w3.6: v1(512.55,1221.55) v1(512.55,1221.55) 612.69,1321.62 720.46,1321.62 795.25,1321.62 823.34,1293.53 868.72,1293.53 883.6,1278.65 883.6,1258.58 874.52,1249.49 861.64,1249.49 852.21,1240.06 852.21,1226.06 844.17,1218.02 821.4,1218.02 v1(806.49,1203.11)
NetR85_2: R85.2 U1.A14 | length 148.3
  Top Layer w5.8: U1.A14@1198.61,1564.41 1198.61,1600.49 1225.16,1627.03 1225.16,1629.65 1225.16,1635.91 1262.58,1673.33 1262.58,1684.25 R85.2@1263.96,1685.63
NetR108_2: R108.2 U1.L18 | length 105.9
  Top Layer w5.8: U1.L18@1324.6,1249.45 1326.53,1247.52 1332.94,1247.52 1357.16,1247.5 1365.62,1255.96 R108.2@1426.18,1255.96
NetR110_2: R110.2 U1.L17 | length 145.4
  Top Layer w5.66: 1308.85,1233.7 1390.29,1233.7
  Top Layer w5.8: U1.L17@1293.1,1249.45 1308.85,1233.7 ; 1390.29,1233.7 1411.61,1233.7 1420.03,1225.27 1420.03,1225.21 1425.4,1219.84 R110.2@1426.18,1219.84
NetR129_2: R129.2 U1.A4 | length 110.8
  Top Layer w5.8: R129.2@851.09,1661.69 851.11,1647.04 868.5,1629.65 883.65,1614.49 883.65,1593.93 U1.A4@883.65,1564.41
NetR132_2: R132.2 U1.B4 | length 166.1
  Top Layer w5.66: 867.9,1548.66 867.9,1593.93
  Top Layer w5.8: R132.2@815.09,1661.69 815.09,1647.31 818.25,1644.15 833.55,1644.15 848.06,1629.65 867.9,1609.8 867.9,1593.93 ; 867.9,1548.66 U1.B4@883.65,1532.91
NetR140_2: R140.2 R237.2 U1.R3 | length 272.8
  Top Layer w5.8: v1(836.41,1107.71) U1.R3@852.16,1123.46
  Bottom Layer w5.8: R140.2@787.59,970.8 786.95,971.43 R237.2@750.06,971.43 750.04,985.3 748,987.34 738.08,997.27 738.08,1061.96 768.34,1092.23 820.92,1092.23 v1(836.41,1107.71)
NetR148_1: R148.1 U1.T4 | length 55.9
  Top Layer w5.8: v1(867.9,1076.22) U1.T4@883.65,1091.97
  Bottom Layer w5.8: R148.1@864.06,1043.77 865.84,1045.56 865.84,1074.15 v1@867.62,1075.94
NetR162_2: R162.2 U1.C4 | length 99.3
  Top Layer w5.8: v1(867.91,1517.16) U1.C4@883.65,1501.41
  Bottom Layer w5.8: R162.2@867.9,1594.01 867.91,1517.57 v1@868.31,1517.16
NetR165_2: R165.2 U1.U3 | length 242.9
  Top Layer w4.2: R165.2@720.37,897.92 713.12,905.17 711.6,905.17 709.14,907.63 709.14,912.06 717,919.92 743.54,919.92 837.13,1013.52 837.13,1045.45 U1.U3@852.16,1060.47
NetR168_2: R168.2 U1.V2 | length 207.6
  Top Layer w4.2: R168.2@689.31,897.92 696.56,905.17 698.08,905.17 700.54,907.63 700.54,915.62 713.44,928.52 739.97,928.52 827.55,1016.09 827.55,1020.74 820.66,1027.63 U1.V2@820.66,1028.97
NetR174_2: R174.2 U1.N2 | length 267.6
  Top Layer w5.66: 779.91,1170.75 804.96,1170.75
  Top Layer w5.8: R174.2@620,1053.86 620,1074.43 683.77,1138.2 738.11,1138.2 752.28,1152.37 761.54,1152.37 779.91,1170.75 ; 804.96,1170.75 U1.N2@820.66,1186.45
NetR210_1: R210.1 U5.8 | length 79.5
  Top Layer w5.8: R210.1@151.15,404.28 151.15,445.5 155.66,450.01 187.49,450.01 U5.8@187.54,450.05
NetR213_1: R213.1 U5.5 | length 58.8
  Top Layer w5.8: R213.1@147.24,548.34 147.24,532.83 150.37,529.69 150.37,529.43 153.24,526.56 U5.5@187.8,526.56
NetR214_2: R214.2 R215.2 U1.A16 | length 1979.1
  Top Layer w5.8: R214.2@1150.47,501.69 1150.47,516.82 1160.38,526.73 1187.72,526.73 v1(1188.53,527.53) ; U1.A16@1261.61,1564.41 1261.61,1565.05 1274.73,1578.18 v1(1274.73,1578.82)
  L03_SIG1 w3.6: v1(1274.73,1578.82) 1274.73,1592.61 1293.68,1611.56 1314.09,1611.56 1323.32,1602.33 1323.32,1577.96 1336.29,1564.99 1383.89,1564.99 1390.29,1571.39 1410.24,1591.34 1474.91,1591.34 1508.47,1557.79 1508.47,1524.46 1533.53,1499.4 1603.32,1499.4 1620.16,1482.56 1620.16,1393.16 1594.55,1367.55 1594.55,810.42 1617.81,787.16 1620.15,784.82 1620.15,719.22 1617.81,716.88 1507.96,607.02 1507.96,548.13 v1(1508.21,547.88)
  L08_SIG2 w3.6: v1(1188.53,527.53) 1208.95,507.12 1332.17,507.12 1394.54,569.49 1486.33,569.49 1507.95,547.88 v1(1508.21,547.88)
  Bottom Layer w5.8: R215.2@1149.41,500.3 1149.41,516.88 1160.07,527.53 v1(1188.53,527.53)
NetR217_2: R217.2 U1.B12 | length 195.1
  Top Layer w5.66: 1151.32,1548.61 1151.32,1608.16
  Top Layer w5.8: U1.B12@1135.62,1532.91 1151.32,1548.61 ; 1151.32,1608.16 1172.81,1629.65 1185.66,1642.5 1185.66,1655 1171.31,1669.35 R217.2@1171.31,1701.31
NetR218_1: R218.1 SW1.8 | length 99.9
  Top Layer w5.8: SW1.8@894.87,2369.54 928.57,2369.54 940,2358.1 v1(940,2357.99)
  Bottom Layer w5.8: R218.1@894.87,2369.54 928.46,2369.54 v1(940,2357.99)
NetR219_1: R219.1 SW1.7 | length 96.6
  Top Layer w5.8: SW1.7@894.87,2319.54 v1(943.15,2319.54)
  Bottom Layer w5.8: R219.1@894.87,2319.54 v1(943.15,2319.54)
NetR220_1: R220.1 SW1.6 | length 96.8
  Top Layer w5.8: SW1.6@894.87,2269.54 904.12,2278.79 v1(939.45,2278.79)
  Bottom Layer w5.8: R220.1@894.87,2269.54 929.96,2269.54 939.21,2278.79 v1(939.45,2278.79)
NetR221_1: R221.1 SW1.5 | length 95.5
  Top Layer w5.8: SW1.5@894.87,2219.54 v1(942.62,2219.54)
  Bottom Layer w5.8: R221.1@894.87,2219.54 v1(942.62,2219.54)
NetR222_1: R222.1 U17.2 U17.3 | length 109.6
  Bottom Layer w5.8: U17.3@623.7,2310.93 657.7,2310.93 664.72,2317.95 ; U17.2@623.7,2326.67 655.99,2326.67 664.72,2317.95 ; R222.1@685.72,2317.95 664.72,2317.95
NetR231_2: R231.2 R232.2 U17.14 U17.15 | length 213.5
  Bottom Layer w5.8: U17.14@391.42,2310.93 427.18,2310.93 435.13,2318.87 ; U17.15@391.42,2326.68 427.32,2326.68 435.13,2318.87 ; R232.2@498.96,2382.89 498.72,2383.13 471.8,2383.13 R231.2@471.56,2383.37 471.56,2334.18 456.25,2318.87 435.13,2318.87
NetR235_2: R235.2 U1.M17 | length 141.2
  Top Layer w5.66: 1308.89,1202.16 1344,1202.16
  Top Layer w5.8: U1.M17@1293.1,1217.95 1308.89,1202.16 ; 1344,1202.16 1360.57,1185.59 1390.29,1185.59 R235.2@1420.87,1185.59
NetR236_2: R236.2 U1.N16 | length 376.6
  Top Layer w5.8: U1.N16@1261.61,1186.45 v1(1277.35,1170.71)
  Bottom Layer w5.8: v1(1277.35,1170.71) 1278.15,1170.71 1296.19,1152.67 1360.43,1152.67 1383.83,1176.08 1383.83,1227.89 1390.29,1234.35 1394.11,1238.17 1417.88,1238.17 1445.75,1210.3 1486.89,1210.3 1518.7,1242.11 R236.2@1533.7,1242.11
NetR246_2: R246.2 R247.2 U21.6 | length 133.2
  Bottom Layer w5.8: R246.2@2790.81,779.4 2790.81,805.1 2800.39,814.68 U21.6@2822.2,814.68 2843.32,814.68 2852.53,805.47 R247.2@2852.53,767.51
NetR269_1: R269.1 U25.6 | length 92.7
  Top Layer w5.8: R269.1@2893.51,1212.6 2938.89,1212.6 2948.83,1202.66 U25.6@2948.83,1169.45
NetR270_1: R270.1 U25.7 U25.8 | length 148.9
  Top Layer w5.8: R270.1@2925,1110.57 2950.59,1110.57 2968.52,1128.5 ; U25.7@2968.52,1169.45 2968.52,1128.5 ; U25.8@2988.2,1169.45 2988.2,1134.76 2981.94,1128.5 2968.52,1128.5
NetR271_2: R271.2 U25.9 | length 66
  Top Layer w5.8: R271.2@3007.89,1103.47 U25.9@3007.89,1169.45
NetR282_2: R282.2 U1.P15 | length 616.2
  Top Layer w5.8: U1.P15@1230.11,1154.96 v1(1245.86,1139.21)
  Bottom Layer w5.8: v1(1245.86,1139.21) 1261.2,1123.86 1261.2,1070.73 1271.49,1060.44 1314.55,1060.44 1354.81,1020.18 1354.81,1000.1 1386.34,968.58 1386.34,949.52 1421.84,914.02 1450.79,914.02 1459.39,922.63 1474.63,922.63 1489.77,907.49 1489.77,812.51 1504.19,798.09 1504.19,743.27 1500.79,739.87 R282.2@1482.88,739.87
NetR310_2: R310.2 U1.T6 | length 83.3
  Top Layer w5.8: v1(930.9,1076.22) U1.T6@946.64,1091.97
  Bottom Layer w5.8: R310.2@902.53,1026.9 902.53,1047.85 v1(930.9,1076.22)
NetR311_1: R311.1 R312.1 U1.P2 | length 962.2
  Top Layer w5.8: v1(804.91,1139.21) U1.P2@820.66,1154.96
  L03_SIG1 w3.6: v1(523.91,1110.76) 523.91,1176.31 492.86,1207.36 492.86,1232.02 503.85,1243.01 519.6,1243.01 639.78,1363.2 779.01,1363.2 832.04,1310.16 885.85,1310.16 915.17,1280.85 915.17,1255.8 908.49,1249.13 906.17,1249.13 905.9,1249.4 892.9,1249.4 883.7,1240.2 883.7,1225.88 875.82,1218 863.62,1218 ; v1(804.91,1139.21) 804.91,1166.36 825.12,1186.57 842.91,1186.57 843.35,1187 843.61,1187 852.21,1195.6 852.21,1208.77 861.4,1217.97 863.59,1217.97
  Bottom Layer w5.8: R311.1@475.11,1147.37 R312.1@513.3,1147.37 513.3,1121.36 v1(523.91,1110.76)
NetS2_3: S2.3 U11.15 U11.16 | length 191.2
  Top Layer w10: v1(1583.55,548.4) 1641.24,548.4 1649.06,556.22 S2.3@1649.06,595.47
  Bottom Layer w10: v1(1583.55,548.4) 1584.5,548.4 1595.18,559.08 1620.35,559.08 U11.15@1621.45,560.18 ; v1@1585.47,546.43 1595.61,536.28 1619.68,536.28 U11.16@1621.11,534.85
NetU1_T5: U1.T5 U20.9 | length 656.9
  Top Layer w5.8: v1(660.02,617.57) 663.32,617.57 671.12,625.37 U20.9@708.96,625.37 ; v1(899.4,1076.22) U1.T5@915.15,1091.97
  L03_SIG1 w3.6: v1(660.02,617.57) 661.79,619.34 678.13,635.68 700.89,635.68 708.82,643.61 708.82,711.5 734.77,737.45 734.77,755.35 721.15,768.97 721.15,873.2 721.15,880.46 828.03,987.34 899.4,1058.71 v1(899.4,1076.22)
nRESET: J5.6 R64.2 | length 116.4
  Top Layer w5.8: J5.6@2588.18,1749.78 2641.07,1749.78 2651.34,1739.52 2669.75,1739.52 2678.18,1731.09 R64.2@2678.18,1712.47
OSPI0_CLK: R174.1 R201.2 U15.B2 | length 1281.8
  Top Layer w5.8: U15.B2@182.96,908.61 199.55,892.02 263.13,892.02 281.38,873.76 v1(281.38,857.95) ; v1(557.29,1053.71) 557.37,1053.78 579.57,1053.78 R174.1@579.64,1053.86
  L08_SIG2 w3.6: v1(281.38,857.95) 233.63,905.7 128.85,905.7 78.24,956.31 78.24,972.37 91.03,985.16 114.27,985.16 163.54,935.88 175.58,935.88 177.38,935.88 180.1,938.6 180.1,965.63 182.82,968.35 190.98,968.35 193.7,965.63 193.7,933.67 196.42,930.95 204.58,930.95 207.3,933.67 207.3,965.63 210.02,968.35 218.18,968.35 220.9,965.63 220.9,933.67 223.62,930.95 231.78,930.95 234.5,933.67 234.5,965.63 237.22,968.35 245.38,968.35 248.1,965.63 248.1,933.67 250.82,930.95 258.98,930.95 261.7,933.67 261.7,963.54 264.42,966.26 272.58,966.26 275.3,963.54 275.3,938.6 280.07,933.83 419.83,933.83 495.69,1009.69 533.94,1009.69 557.29,1033.04 v1(557.29,1053.71)
  Bottom Layer w5.8: v1(557.29,1053.71) 571.37,1053.71 579.53,1045.55 R201.2@597.6,1045.55
OSPI0_CSN0: R184.2 U1.P1 U15.C2 | length 1481.5
  Top Layer w5.8: U15.C2@222.33,908.61 241.11,927.39 323.07,927.39 384.76,989.07 v1(507.18,989.07) ; v1(773.42,1139.21) U1.P1@789.16,1154.96
  Bottom Layer w5.8: v1(507.18,989.07) 516.35,979.9 R184.2@537.17,979.9 ; R184.2@537.27,979.99 553.71,979.99 557.52,976.18 557.52,926.48 569,915 569,822.43 592.54,798.9 592.54,728.72 573.15,709.33 573.15,604.79 581.19,596.75 601.77,596.75 611.86,606.84 611.86,800.84 588.88,823.83 588.88,917.8 597.07,926 629.03,926 694.2,991.17 708.21,991.17 720.46,1003.42 720.46,1061.41 773.42,1114.37 v1(773.42,1139.21)
OSPI0_D0: R182.1 R186.2 R223.1 U1.N1 | length 1299.7
  Top Layer w5.8: R186.2@350.94,1124.69 R182.1@350.94,1164.69 352.91,1166.66 R223.1@352.91,1215.63 395.91,1215.63 v1(414.67,1196.87) ; v1(758.04,1171.28) 773.21,1186.45 U1.N1@789.16,1186.45
  L08_SIG2 w3.6: v1(414.67,1196.87) 389.54,1222 338,1222 316.58,1200.58 316.58,1185.39 341.36,1160.61 389.87,1160.61 394.95,1155.52 394.95,1150 390.6,1145.65 376.71,1145.65 370.81,1139.74 370.81,1112.81 359.73,1101.73 330.6,1101.73 310.8,1121.53 310.8,1171.4 299,1183.2 299,1214.45 337.6,1253.05 404.4,1253.05 415.41,1264.05 588.6,1264.05 647.36,1322.81 712.69,1322.81 718.42,1317.08 730.77,1317.08 770.22,1277.63 770.22,1183.46 v1(758.04,1171.28)
OSPI0_D1: R181.1 R187.2 R224.1 U1.N4 | length 1368.9
  Top Layer w5.8: R187.2@448.8,893.76 R181.1@487.79,893.76 488.88,894.85 488.88,904.58 482.98,910.48 v1(482.98,913.74) ; v1(867.9,1170.71) U1.N4@883.65,1186.45
  L08_SIG2 w3.6: v1@482.98,913.78 470.28,926.47 457.37,926.47 447.35,916.45 447.35,861.34 459.26,849.43 508.69,849.43 543.71,884.44 575.23,884.44 589.7,869.98 707.48,869.98 744.97,907.47 953.42,907.47 989.08,943.12 1004.54,943.12 1017.97,956.55 1017.97,971.76 1001.92,987.8 932.7,987.8 921.69,998.81 921.69,1031.15 911.91,1040.92 813.73,1040.92 775.71,1078.95 775.71,1111.38 787.84,1123.51 874.41,1123.51 883.8,1132.9 883.8,1154.81 v1@868.1,1170.51
  Bottom Layer w5.8: v1(482.98,913.74) 486.28,913.74 491.54,919 499,919 504,914 R224.1@504,901
OSPI0_D2: R180.1 R189.2 U1.M4 | length 1346.1
  Top Layer w5.8: R189.2@199,1133.69 R180.1@199,1182.04 217.91,1182.04 224.45,1175.49 v1(224.45,1156.44) ; v1(867.91,1202.27) U1.M4@883.62,1217.95
  L08_SIG2 w3.6: v1(224.45,1156.44) 224.45,1156.6 190.78,1190.28 190.78,1358.96 205.46,1373.64 228.65,1373.64 240.77,1361.52 240.77,1346.77 234,1340 234,1255.12 255.45,1233.67 288.87,1233.67 333.59,1278.4 368.1,1278.4 398.12,1308.42 584.5,1308.42 636.6,1360.52 720.46,1360.52 740.85,1360.52 750.62,1350.75 750.62,1325.52 789.89,1286.25 789.89,1195.91 799.23,1186.57 852.21,1186.57 867.84,1202.2 v1@867.91,1202.2
OSPI0_D3: R179.1 R191.2 U1.P3 | length 1377.4
  Top Layer w5.8: R191.2@246.98,1129.94 R179.1@246.98,1172.98 262.23,1172.98 266.54,1168.67 266.54,1158.4 274.5,1150.44 v1(274.5,1148.9) ; v1(836.41,1139.21) U1.P3@852.16,1154.96
  L08_SIG2 w3.6: v1(274.5,1148.9) 256.8,1148.9 201.72,1203.98 201.72,1353.44 207.67,1359.38 217.67,1359.38 221.39,1355.66 221.39,1228.62 237.93,1212.08 237.93,1188.56 242.89,1183.6 255.72,1183.6 259.53,1187.4 259.53,1214.71 262.79,1217.97 286.74,1217.97 334.14,1265.37 368.65,1265.37 402.1,1298.82 599.92,1298.82 649.09,1348 708.49,1348 720.46,1336.03 729.81,1326.68 734.74,1326.68 779.82,1281.61 779.82,1189.67 812.21,1157.28 818.34,1157.28 v1(836.41,1139.21)
OSPI0_D4: R178.1 R193.2 U1.M1 | length 1405.3
  Top Layer w5.8: v1(285.16,1173.09) 308.85,1173.09 R178.1@308.96,1172.98 308.96,1159.13 298.96,1149.13 R193.2@298.96,1131.69 ; v1(698.42,1190.83) 715.05,1190.83 720.46,1185.43 726.29,1179.6 737.77,1179.6 746.87,1188.69 751.06,1188.69 771.86,1209.5 780.72,1209.5 U1.M1@789.16,1217.95
  L08_SIG2 w3.6: v1(285.16,1173.09) 300,1158.25 300,1130 287,1117 206.11,1117 173.63,1149.48 173.63,1188.25 168.59,1193.29 160.36,1193.29 156.28,1189.21 156.28,1108.23 164.06,1100.45 214.88,1100.45 237.34,1078 369.63,1078 427.69,1136.07 436.37,1136.07 494.63,1194.32 494.63,1231.62 505.41,1242.4 597.5,1242.4 650.66,1295.56 673.36,1295.56 695.14,1273.79 738.5,1273.79 759.81,1252.48 759.81,1195.26 736.67,1172.12 704.19,1172.12 698.42,1177.89 v1(698.42,1190.83)
OSPI0_D5: R177.1 R195.2 U1.L1 | length 1349.2
  Top Layer w5.8: R195.2@449.67,1013.96 R177.1@488.03,1013.96 v1@488.03,1037.21 ; v1(711.16,1219.15) 711.96,1218.35 740.47,1218.35 771.57,1249.45 U1.L1@789.16,1249.45
  L08_SIG2 w3.6: v1(487.96,1037.27) 487.96,1023.25 411.71,947 315.55,947 274.55,988 204.58,988 197.79,994.79 197.79,1002.34 203.15,1007.7 320.01,1007.7 331.7,996 412,996 484.42,1068.42 540.71,1068.42 637.97,1165.68 637.97,1231.9 666.7,1260.63 738.08,1260.63 750.21,1248.5 750.21,1199.24 737.66,1186.69 720.74,1186.69 715.22,1192.21 715.22,1197.79 711.16,1201.85 v1(711.16,1219.15)
OSPI0_D6: R176.1 R196.2 U1.L2 | length 1356.6
  Top Layer w5.6: R196.2@448.8,960.62 R176.1@488.56,960.62 488.45,960.52 v1(488.45,939.62)
  Top Layer w5.66: 779.29,1233.74 804.96,1233.74
  Top Layer w5.8: v1(730.9,1202.39) 747.93,1202.39 779.29,1233.74 ; 804.96,1233.74 U1.L2@820.66,1249.45
  L08_SIG2 w3.6: v1(488.45,939.62) 488.45,938.55 518.64,908.36 589.65,908.36 608.82,889.18 699.53,889.18 765.35,955 812.38,955 828,970.62 828,1005.16 812.97,1020.19 806,1020.19 804.2,1020.19 801.48,1017.47 801.48,990.06 798.76,987.34 790.6,987.34 787.88,990.06 787.88,1021.21 785.16,1023.93 777,1023.93 774.28,1021.21 774.28,990.06 771.56,987.34 763.4,987.34 760.68,990.06 760.68,1021.21 757.96,1023.93 749.8,1023.93 747.08,1021.21 747.08,990.06 744.36,987.34 736.2,987.34 733.48,990.06 733.48,1017.47 730.76,1020.19 721,1020.19 692.33,1020.19 681,1031.52 681,1038.37 681,1053.77 683.72,1056.49 704.84,1056.49 707.56,1059.21 707.56,1067.37 704.84,1070.09 680.23,1070.09 677.51,1072.81 677.51,1080.97 680.23,1083.69 704.5,1083.69 707.22,1086.41 707.22,1094.57 704.5,1097.29 683.72,1097.29 681,1100.01 681,1106 681,1150 658.03,1172.97 658.03,1224.86 669.12,1235.95 718.36,1235.95 730.9,1223.41 v1(730.9,1202.39)
OSPI0_D7: R175.1 R197.2 U1.K1 | length 1353.6
  Top Layer w5.8: R197.2@448.8,848.86 448.8,863.91 455.02,870.13 486.11,870.13 v1(487.52,868.72) R175.1@487.52,848.99 ; v1(674.84,1217.88) 674.84,1231.84 713.03,1270.02 720.46,1270.02 737.06,1270.02 747.69,1280.65 U1.K1@788.87,1280.65
  L08_SIG2 w3.6: v1(487.52,868.72) 514.04,895.24 583.76,895.24 599.42,879.58 703.51,879.58 768.11,944.18 841.82,944.18 866,920 903.06,920 906.35,923.3 906.35,930.56 902.87,934.04 870.2,934.04 867.48,936.76 867.48,944.92 870.2,947.64 905.48,947.64 908.2,950.36 908.2,958.52 905.48,961.24 870.2,961.24 867.48,963.96 867.48,972.12 870.2,974.84 902.87,974.84 905.59,977.56 905.59,1019.61 894.21,1030.99 876.68,1030.99 873.96,1028.27 873.96,1015.99 871.24,1013.27 863.08,1013.27 860.36,1015.99 860.36,1028.27 857.64,1030.99 849.48,1030.99 846.76,1028.27 846.76,1015.99 844.04,1013.27 835.88,1013.27 833.16,1015.99 833.16,1028.27 830.11,1031.32 808.06,1031.32 755.57,1083.82 755.57,1117.12 744.19,1128.5 726.31,1128.5 674.84,1179.97 v1(674.84,1217.88)
OSPI0_DQS: R183.1 R198.2 R199.1 R200.2 U1.M3 | length 1246
  Top Layer w5.8: R199.1@78.91,1268.28 78.91,1226.18 84.26,1220.84 99.04,1220.84 R183.1@99.13,1220.75 R198.2@99.13,1120.75 ; R199.1@79.05,1268.41 97.41,1268.41 102,1273 102,1291.25 116.85,1306.1 166.9,1306.1 200.7,1272.31 v1(284.24,1272.31) ; v1(836.41,1202.27) U1.M3@852.13,1217.95
  L08_SIG2 w3.6: v1(284.24,1272.31) 257.85,1272.31 248.7,1281.45 248.7,1336.5 270.81,1358.61 491.49,1358.61 505.1,1372.21 720.46,1372.21 745.94,1372.21 760.22,1357.93 760.22,1329.5 803.82,1285.9 803.82,1234.79 v1@836.41,1202.2
OSPI0_ECS: R185.1 U1.H1 U15.A5 | length 972.3
  Top Layer w5.8: v1(96.8,1044.13) 126.18,1044.13 U15.A5@143.59,1026.72 ; v1(654.27,1271.96) 654.27,1300.82 713.11,1359.66 720.46,1359.66 749.2,1359.66 764.93,1343.93 U1.H1@789.16,1343.93
  L08_SIG2 w3.6: v1(96.8,1044.13) 122.61,1044.13 132.91,1033.83 379.76,1033.83 425.59,1079.66 455.26,1079.66 503.15,1127.56 550.69,1127.56 580.75,1157.62 580.75,1198.44 v1(654.27,1271.96)
  Bottom Layer w5.8: v1@483.82,1107.73 483.82,1094.01 489.21,1088.62 R185.1@489.21,1070.59
  other v1: 483.57,1107.97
